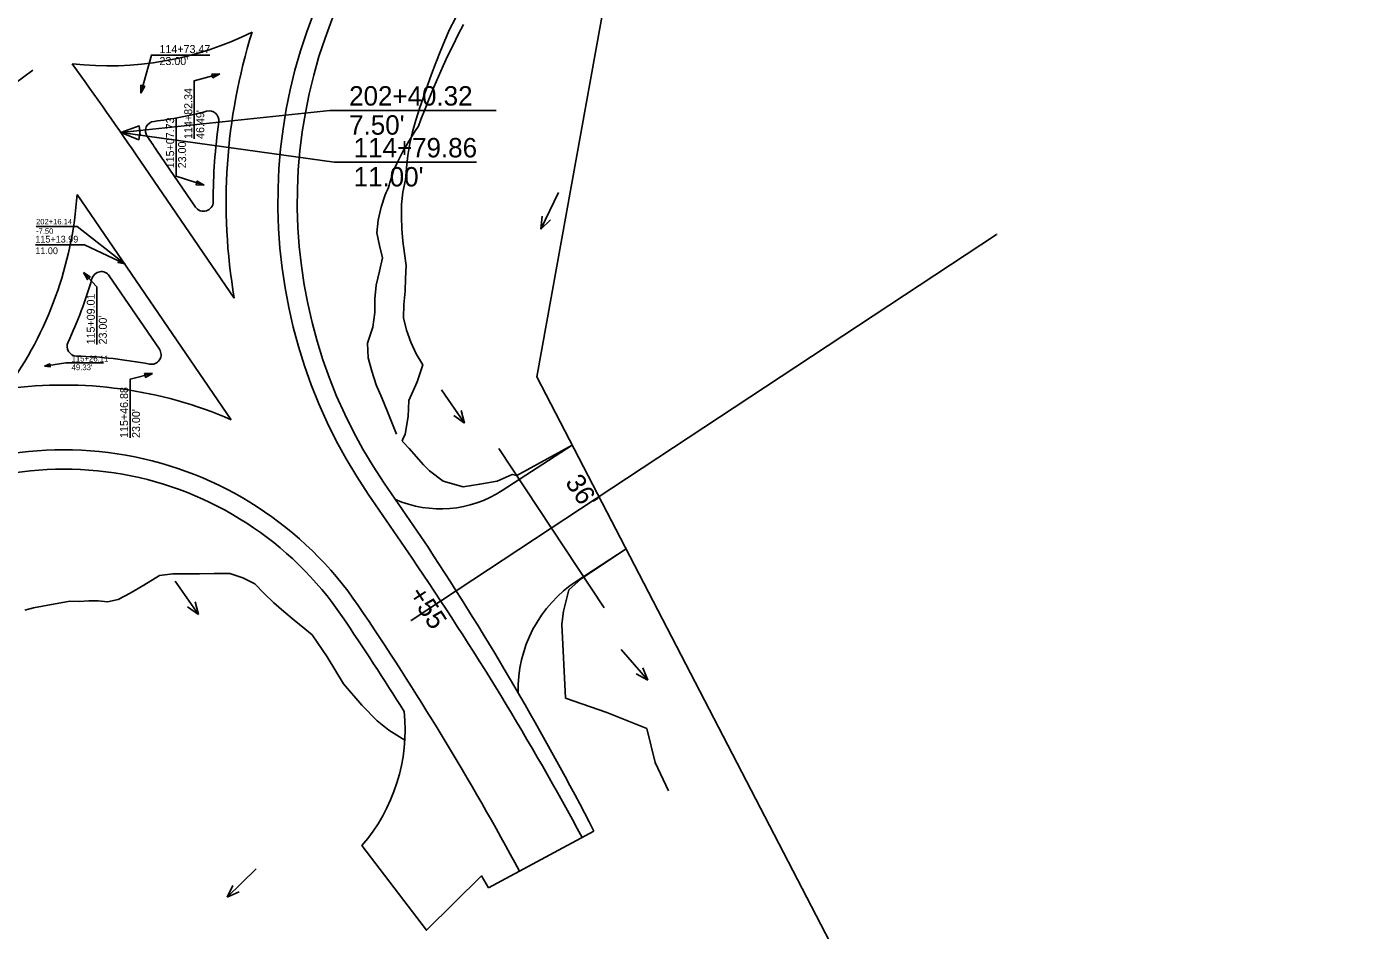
# Model space of a CAD drawing. Extents: x 1006695 to 1009377, y 1883329 to 1886115.
# Drawn here: x 1008057.5 to 1008468.1, y 1884258 to 1884537.5 of the extents above; entities that cross this region are included whole.
import ezdxf

# ---------------------------------------------------------------- set-up
doc = ezdxf.new("R2010")
doc.units = 0
for name, color, linetype in [('Default', 7, 'Continuous'), ('OLD RAMP 2', 7, 'Continuous'), ('R_Drive', 7, 'Continuous'), ('R_No Plot', 7, 'Continuous'), ('R_Prop Const Limits Cut', 7, 'Continuous'), ('R_Prop Curb', 7, 'Continuous'), ('R_Prop EOL', 7, 'Continuous'), ('R_Prop EOL NPLT', 7, 'Continuous'), ('R_Prop EOS', 7, 'Continuous'), ('R_Proposed Road', 7, 'Continuous'), ('R_Water Annot', 7, 'Continuous'), ('S_EXIST_ROW', 7, 'Continuous')]:
    doc.layers.add(name, color=color, linetype=linetype)

msp = doc.modelspace()

# ---------------------------------------------------------------- linework, layer by layer
at = {"layer": 'OLD RAMP 2'}
msp.add_lwpolyline([(1008171.92, 1884411.42), (1008170.63, 1884414.54), (1008169.06, 1884418.7), (1008167.36, 1884422.74), (1008165.65, 1884426.75), (1008164.32, 1884430.92), (1008163.11, 1884435.1), (1008162.93, 1884439.61), (1008164.54, 1884444.59), (1008165.19, 1884449.09), (1008165.2, 1884453.32), (1008165.64, 1884457.57), (1008166.63, 1884461.83), (1008167.55, 1884465.96), (1008166.67, 1884469.82), (1008165.84, 1884473.71), (1008166.25, 1884477.68), (1008167.18, 1884481.61), (1008168.41, 1884485.48), (1008168.72, 1884486.24), (1008169.08, 1884486.99), (1008169.38, 1884487.74), (1008169.39, 1884487.74), (1008169.61, 1884488.5), (1008169.82, 1884489.25), (1008170.53, 1884491.49), (1008171.01, 1884492.97), (1008171.96, 1884495.14), (1008173.75, 1884498.68), (1008175.71, 1884502.1), (1008177.82, 1884505.4), (1008178.71, 1884506.7), (1008179.43, 1884508.74), (1008180.74, 1884512.12), (1008182.11, 1884515.45), (1008183.46, 1884518.78), (1008184.86, 1884522.08), (1008186.31, 1884525.35), (1008187.81, 1884528.59), (1008189.38, 1884531.81), (1008190.99, 1884535.01), (1008192.64, 1884538.2)], dxfattribs=at)
at = {"layer": 'R_Drive'}
for p, q in [((1008204.56, 1884393.99), (1008226.24, 1884408.06)), ((1008227.73, 1884366.11), (1008242.89, 1884375.95))]:
    msp.add_line(p, q, dxfattribs=at)
msp.add_lwpolyline([(1008161.22, 1884284.21), (1008181.16, 1884258.03), (1008198.18, 1884274.86), (1008200.38, 1884271.14)], dxfattribs=at)
for centre, radius, start, end in [((1008185.5, 1884423.35), 35, 246.5288, 302.9841), ((1008249.51, 1884332.55), 40, 122.9841, 181.5964), ((1008119.56, 1884320.11), 55, 319.2442, 5.8032)]:
    msp.add_arc(centre, radius, start, end, dxfattribs=at)
at = {"layer": 'R_No Plot'}
for p, q in [((1008098.62, 1884528.7), (1008114.16, 1884528.7)), ((1008039.29, 1884509.29), (1008059.51, 1884523.99)), ((1008109.37, 1884502.76), (1008109.37, 1884518.3)), ((1008103.77, 1884493.68), (1008103.77, 1884509.41)), ((1008157.26, 1884511.58), (1008202.69, 1884511.58)), ((1008158.66, 1884495.56), (1008196.68, 1884495.56)), ((1008060.47, 1884475.72), (1008071.75, 1884475.72)), ((1008176.4, 1884353.81), (1008357.43, 1884473.21)), ((1008060.24, 1884469.96), (1008073.62, 1884469.96)), ((1008079.24, 1884439.21), (1008079.24, 1884454.56)), ((1008071.44, 1884433.48), (1008081.34, 1884433.48)), ((1008089.52, 1884410.29), (1008089.52, 1884425.95)), ((1008203.59, 1884407.03), (1008236.12, 1884357.71))]:
    msp.add_line(p, q, dxfattribs=at)
for points in [[(1008092.83, 1884516.9), (1008096.15, 1884528.7), (1008098.62, 1884528.7)], [(1008117.29, 1884522.87), (1008109.37, 1884520.77), (1008109.37, 1884518.3)], [(1008086.68, 1884504.74), (1008151.26, 1884511.58), (1008157.26, 1884511.58)], [(1008086.68, 1884504.74), (1008152.66, 1884495.56), (1008158.66, 1884495.56)], [(1008112.4, 1884488.45), (1008103.77, 1884491.2), (1008103.77, 1884493.68)], [(1008087.86, 1884464.1), (1008073.2, 1884475.72), (1008071.75, 1884475.72)], [(1008087.86, 1884464.1), (1008075.41, 1884469.96), (1008073.62, 1884469.96)], [(1008075.14, 1884461.44), (1008079.24, 1884457.03), (1008079.24, 1884454.56)], [(1008063.05, 1884432.47), (1008069.65, 1884433.48), (1008071.44, 1884433.48)], [(1008096.51, 1884430.18), (1008089.52, 1884428.42), (1008089.52, 1884425.95)]]:
    msp.add_lwpolyline(points, dxfattribs=at)
for points in [[(1008117.29, 1884522.87), (1008115.13, 1884521.68), (1008114.82, 1884522.84)], [(1008092.83, 1884516.9), (1008092.9, 1884519.37), (1008094.06, 1884519.05)], [(1008086.68, 1884504.74), (1008092.32, 1884506.8), (1008092.63, 1884503.9)], [(1008086.68, 1884504.74), (1008092.65, 1884505.38), (1008092.25, 1884502.49)], [(1008112.4, 1884488.45), (1008109.93, 1884488.61), (1008110.29, 1884489.75)], [(1008087.86, 1884464.1), (1008085.81, 1884464.5), (1008086.24, 1884465.42)], [(1008087.86, 1884464.1), (1008086.31, 1884464.8), (1008086.82, 1884465.44)], [(1008075.14, 1884461.44), (1008077.21, 1884460.09), (1008076.33, 1884459.28)], [(1008063.05, 1884432.47), (1008064.7, 1884433.16), (1008064.84, 1884432.3)], [(1008096.51, 1884430.18), (1008094.32, 1884429.01), (1008094.03, 1884430.17)]]:
    msp.add_lwpolyline(points, close=True, dxfattribs=at)
at = {"layer": 'R_Prop Const Limits Cut'}
for points in [[(1008188.28, 1884536.62), (1008190.02, 1884539.92), (1008191.68, 1884543.27), (1008193.56, 1884546.51)], [(1008173.9, 1884486.32), (1008174.66, 1884490.08), (1008174.98, 1884493.84), (1008175.38, 1884497.59), (1008176.02, 1884501.3), (1008176.81, 1884504.99), (1008177.88, 1884508.61), (1008179.03, 1884512.19), (1008180.27, 1884515.72), (1008181.47, 1884519.26), (1008182.72, 1884522.77), (1008184.02, 1884526.26), (1008185.38, 1884529.73), (1008186.8, 1884533.18), (1008188.28, 1884536.62)], [(1008173.7, 1884409.32), (1008173.88, 1884409.95), (1008174.63, 1884411.43), (1008175.56, 1884416.95), (1008175.72, 1884421.84), (1008178.25, 1884427.69), (1008180.01, 1884432.88), (1008178, 1884436.3), (1008176.32, 1884439.89), (1008174.96, 1884443.61), (1008174.02, 1884447.45), (1008174.14, 1884451.57), (1008174.55, 1884455.67), (1008174.73, 1884459.65), (1008174.92, 1884463.57), (1008174.34, 1884467.33), (1008173.89, 1884471.11), (1008173.59, 1884474.91), (1008173.44, 1884478.72), (1008173.42, 1884482.53), (1008173.9, 1884486.32)], [(1008180.27, 1884402.01), (1008175.81, 1884406.98), (1008174, 1884408.99), (1008173.7, 1884409.32)], [(1008192.53, 1884395.12), (1008197.66, 1884396.04), (1008203.07, 1884396.93), (1008207.7, 1884398.99), (1008209.1, 1884398.68), (1008226.24, 1884408.06)], [(1008180.27, 1884402.01), (1008182.15, 1884400.14), (1008186.35, 1884396.96), (1008192.53, 1884395.12)], [(1008242.89, 1884375.95), (1008229, 1884366.69), (1008225.23, 1884363.32), (1008223.58, 1884356.75), (1008223.01, 1884352.73)], [(1008056.98, 1884357.06), (1008059.71, 1884357.72), (1008062.48, 1884358.26), (1008065.27, 1884358.75), (1008068.08, 1884359.27), (1008070.95, 1884359.83), (1008073.81, 1884359.66), (1008076.74, 1884359.91), (1008079.68, 1884359.94), (1008082.6, 1884359.64), (1008085.81, 1884360.36), (1008089.53, 1884362.24), (1008093.77, 1884364.75), (1008098.58, 1884367.76), (1008102.7, 1884368.31), (1008106.76, 1884368.29), (1008111.03, 1884368.31), (1008115.58, 1884368.38), (1008120.33, 1884368.34), (1008124.35, 1884366.98), (1008128.12, 1884365.13), (1008131.01, 1884362.21), (1008133.94, 1884359.34), (1008137.1, 1884356.66), (1008140.31, 1884353.95), (1008143.6, 1884351.21), (1008145.79, 1884349.4)], [(1008223.01, 1884352.73), (1008224.12, 1884329.84)], [(1008145.79, 1884349.4), (1008150.51, 1884342.56), (1008155.47, 1884334.2), (1008161.21, 1884327.69), (1008165.95, 1884322.77), (1008169.5, 1884319.88), (1008174.46, 1884316.84)], [(1008224.12, 1884329.84), (1008236.96, 1884325.39), (1008249.28, 1884320.43), (1008251.84, 1884309.89), (1008256.01, 1884301.15)]]:
    msp.add_lwpolyline(points, dxfattribs=at)
at = {"layer": 'R_Prop Curb'}
for p, q in [((1008109.75, 1884481.69), (1008097.71, 1884499.31)), ((1008083.09, 1884460.44), (1008098.6, 1884437.75))]:
    msp.add_line(p, q, dxfattribs=at)
for centre, radius, start, end in [((1008082.8, 1884625.35), 118, 276.8772, 284.9278), ((1008113.97, 1884508.44), 3, 352.0835, 104.9278), ((1008097.29, 1884505.22), 3, 96.8772, 214.5521), ((1008295.23, 1884483.23), 180, 172.0835, 179.9525), ((1006901.08, 1883681.49), 1449.39, 34.35019, 34.5521), ((1008112.23, 1884483.38), 3, 214.3502, 359.9525), ((1007957.43, 1884493.52), 125, 334.5942, 344.2338), ((1008080.62, 1884458.74), 3, 34.3502, 164.2338), ((1008073.05, 1884438.61), 3, 154.5942, 268.3842), ((1008069.05, 1884296.66), 139, 79.0101, 88.3842), ((1008096.12, 1884436.06), 3, 259.0101, 34.3502)]:
    msp.add_arc(centre, radius, start, end, dxfattribs=at)
at = {"layer": 'R_Prop EOL'}
for centre, radius, start, end in [((1008295.23, 1884483.23), 160, 142.6519, 214.3502), ((1008069.05, 1884296.66), 110, 34.1889, 125.6982), ((1007379.23, 1883828.06), 965.93, 28.35049, 34.35019), ((1007379.23, 1883828.06), 943.93, 28.3505, 34.18886)]:
    msp.add_arc(centre, radius, start, end, dxfattribs=at)
at = {"layer": 'R_Prop EOL NPLT'}
for p, q in [((1008092.75, 1884495.92), (1008121.76, 1884453.49)), ((1008073.16, 1884485.6), (1008120.78, 1884415.93)), ((1008163.13, 1884392.95), (1008176.71, 1884373.08))]:
    msp.add_line(p, q, dxfattribs=at)
for centre, radius, start, end in [((1008082.8, 1884625.35), 100, 263.5978, 296.3927), ((1008295.23, 1884483.23), 176, 162.6297, 189.7302), ((1006901.08, 1883681.49), 1443.39, 34.35019, 35.80792), ((1007957.43, 1884493.52), 116, 324.0703, 356.0848), ((1006901.08, 1883681.49), 1421.39, 34.35019, 34.45079), ((1008069.05, 1884296.66), 130, 66.5517, 97.8199)]:
    msp.add_arc(centre, radius, start, end, dxfattribs=at)
at = {"layer": 'R_Prop EOS'}
msp.add_line((1008168.08, 1884396.34), (1008181.66, 1884376.47), dxfattribs=at)
for centre, radius, start, end in [((1008295.23, 1884483.23), 154, 142.6519, 214.3502), ((1008069.05, 1884296.66), 104, 34.1889, 125.6982), ((1007370.03, 1883843.16), 971.16, 27.30892, 33.30863), ((1007379.23, 1883828.06), 937.93, 32.04225, 34.18886)]:
    msp.add_arc(centre, radius, start, end, dxfattribs=at)
at = {"layer": 'R_Proposed Road'}
msp.add_line((1008232.96, 1884288.72), (1008200.38, 1884271.14), dxfattribs=at)
at = {"layer": 'R_Water Annot'}
for p, q in [((1008221.97, 1884486.18), (1008216.55, 1884474.84)), ((1008216.55, 1884474.84), (1008216.94, 1884478.92)), ((1008216.55, 1884474.84), (1008219.47, 1884477.71)), ((1008185.82, 1884425.2), (1008192.91, 1884414.82)), ((1008192.91, 1884414.82), (1008191.89, 1884418.79)), ((1008192.91, 1884414.82), (1008189.58, 1884417.21)), ((1008103.48, 1884365.97), (1008110.68, 1884355.67)), ((1008110.68, 1884355.67), (1008107.33, 1884358.02)), ((1008110.68, 1884355.67), (1008109.62, 1884359.63)), ((1008241.33, 1884344.86), (1008249.57, 1884335.37)), ((1008249.57, 1884335.37), (1008246, 1884337.36)), ((1008249.57, 1884335.37), (1008248.11, 1884339.19)), ((1008128.5, 1884277), (1008119.51, 1884268.22)), ((1008119.51, 1884268.22), (1008121.29, 1884271.91)), ((1008119.51, 1884268.22), (1008123.24, 1884269.9))]:
    msp.add_line(p, q, dxfattribs=at)
at = {"layer": 'S_EXIST_ROW'}
for p, q in [((1008215.28, 1884429.19), (1008237.31, 1884551.2)), ((1008468.08, 1883941.67), (1008215.28, 1884429.19))]:
    msp.add_line(p, q, dxfattribs=at)

# ---------------------------------------------------------------- texts
at = {"layer": 'Default'}
msp.add_text('+', height=1, rotation=33.4061, dxfattribs=at).set_placement((1008357.43, 1884472.61))
at = {"layer": 'R_Drive'}
for s, rotation, p in [("36'", 303.4061, (1008223.87, 1884396.54)), ('+55', 303.0693, (1008175.41, 1884361.95))]:
    msp.add_text(s, height=6, rotation=rotation, dxfattribs=at).set_placement(p)
at = {"layer": 'R_No Plot'}
for s, height, p in [('114+73.47', 2.474, (1008098.62, 1884529.32)), ("23.00'", 2.474, (1008098.62, 1884525.61)), ('202+16.14', 1.695, (1008060.47, 1884476.33)), ('115+13.99', 2.088, (1008060.24, 1884470.71)), ('-7.50', 1.695, (1008060.47, 1884473.42)), ('11.00', 2.088, (1008060.24, 1884467.13)), ('115+26.11', 1.791, (1008071.44, 1884433.93)), ("49.33'", 1.791, (1008071.44, 1884431.25))]:
    msp.add_text(s, height=height, dxfattribs=at).set_placement(p)
for s, height, rotation, p in [('114+82.34', 2.474, 90, (1008108.75, 1884502.76)), ('202+40.32', 6, 360, (1008157.26, 1884513.08)), ('115+07.73', 2.474, 90, (1008103.15, 1884493.68)), ("46.49'", 2.474, 90, (1008112.46, 1884502.76)), ("7.50'", 6, 360, (1008157.26, 1884504.08)), ("23.00'", 2.474, 90, (1008106.86, 1884493.68)), ('114+79.86', 6, 360, (1008158.66, 1884497.06)), ("11.00'", 6, 360, (1008158.66, 1884488.06)), ('115+09.01', 2.474, 90, (1008078.62, 1884439.21)), ("23.00'", 2.474, 90, (1008082.33, 1884439.21)), ('115+46.88', 2.474, 90, (1008088.9, 1884410.29)), ("23.00'", 2.474, 90, (1008092.61, 1884410.29)), ('+', 1, 33.4061, (1008176.4, 1884353.22))]:
    msp.add_text(s, height=height, rotation=rotation, dxfattribs=at).set_placement(p)

doc.saveas('drawing.dxf')
